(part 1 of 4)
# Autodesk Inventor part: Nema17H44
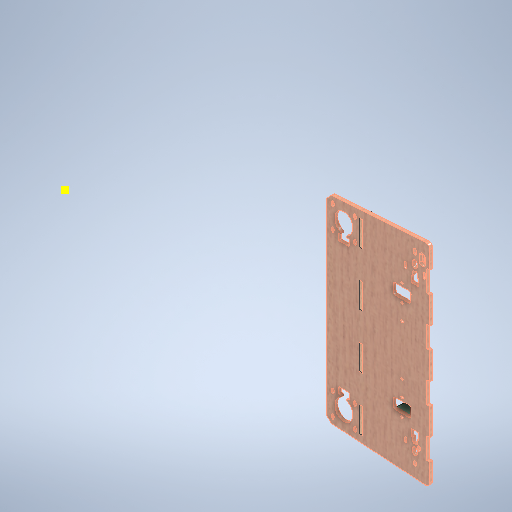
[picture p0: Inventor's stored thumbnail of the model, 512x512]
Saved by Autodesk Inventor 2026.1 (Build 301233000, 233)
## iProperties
Created: 2025-11
Part Number: Nema17H44
Material: Steel
Document SubType Name: Modeling
Designer: Yury Melnikov
Density: 7.85 g/cm^3
Appearance: Резина — зеленая
Mass: 34859.8 g
Surface Area: 7325.72 cm^2
Volume: 4440.74 cm^3
Sending System: Autodesk Translation Framework v14.17.0.0
Preprocessor: ST-DEVELOPER v20.1
Title: m2_20.step
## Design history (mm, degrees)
feature "Body3"
sketch "Эскиз1"
  geometry: L1 (0, 0)-(201.062, 0) reference; L2 (201.062, 0)-(201.062, 16) reference; L3 (0, 16)-(201.062, 16) reference; L4 (0, 0)-(0, 16) reference; C1 r 1.35 at (12.566, 8) reference; C2 r 1.35 at (100.531, 8) reference; C3 r 1.35 at (188.496, 8) reference; 1 further point
  dimensions: "d0" = 87.96459 distance of C2.centre C1.centre (derived); "d1" = 12.56644 distance from line of L4 C1.centre (derived); "d2" = 201.062 distance of L3.start L2.end (derived); "d3" = 16 distance of L1.start L3.start (derived); "d4" = 12.56637 distance from line of L2 C3.centre (derived)
  node "Спроецированная петля1"
pattern_linear "Прямоуг.массив1" dims "d11" = 201
sketch "Эскиз2"
  geometry: L1 (0, 3.5)-(0, 0) reference; L2 (0, 0)-(16, 0) reference; L3 (16, 3.5)-(16, 0) reference; L4 (0, 3.5)-(16, 3.5) reference; L5 (0, 0)-(16, 0); L6 (16, 0)-(16, -200); L7 (16, -200)-(0, -200); L8 (0, -200)-(0, 0); 2 further points
  constraints: 8 end point, 2 parallel, 1 horizontal, 1 perpendicular
  dimensions: "d5" = 16 distance of L6.end L7.end; "d6" = 200 distance of L5.end L6.end
extrude "Выдавливание1" new body sketch "Эскиз2" stored distance "d7" = 1000; taper "d8" = 0 deg
node "РабПлоскость1"
mirror "Зеркальное отражение1"
sketch "Эскиз3"
  geometry: L1 (158, 0)-(-142, 0); L2 (-142, 0)-(-142, 200); L3 (-142, 200)-(158, 200); L4 (158, 200)-(158, 0); L5 (16, 0)-(0, 0) reference; 3 further points
  constraints: 8 end point, 2 midpoint, 2 parallel, 1 coincident, 1 collinear, 1 horizontal, 1 perpendicular
  dimensions: "d12" = 300 distance of L1.start L1.end; "d13" = 200 distance of L1.end L2.end
extrude "Выдавливание2" join sketch "Эскиз3" distance "d14" = 16; taper "d15" = 0 deg
sketch "Эскиз4"
  geometry: L1 (0, 0)-(0, 200) reference; L2 (0, 100)-(107.784, 100); L3 (223.834, 208)-(222.148, 208) reference; L4 (184.75, 229.098)-(215.25, 229.098); L5 (215.25, 229.098)-(215.25, 198.598); L6 (215.25, 198.598)-(184.75, 198.598); L7 (184.75, 198.598)-(184.75, 229.098); L8 (183.233, 235.415)-(216.767, 235.415); L9 (221.567, 230.615)-(221.567, 192.281); L10 (221.567, 192.281)-(178.433, 192.281); L11 (178.433, 192.281)-(178.433, 230.615); L12 (178.433, 230.615)-(183.233, 235.415); L13 (216.767, 235.415)-(221.567, 230.615); L14 (216.767, -35.415)-(221.567, -30.615); L15 (215.25, -29.098)-(215.25, 1.402); L16 (184.75, -29.098)-(215.25, -29.098); L17 (183.233, -35.415)-(216.767, -35.415); L18 (221.567, -30.615)-(221.567, 7.719); L19 (178.433, -30.615)-(183.233, -35.415); L20 (215.25, 1.402)-(184.75, 1.402); L21 (221.567, 7.719)-(178.433, 7.719); L22 (184.75, 1.402)-(184.75, -29.098); L23 (178.433, 7.719)-(178.433, -30.615); L24 (223.834, -8)-(222.148, -8); L25 (343.215, 208)-(341.529, 208) reference; L26 (343.215, -8)-(341.529, -8); L27 (324.365, 208)-(322.679, 208) reference; L28 (321.041, 203.5)-(319.72, 203.5) reference; L29 (226.794, 203.5)-(225.472, 203.5) reference; C1 r 8 at (200, 213.848); C2 r 1.65 at (184.75, 229.098); C3 r 1.65 at (215.25, 229.098); C4 r 1.65 at (184.75, 198.598); C5 r 1.65 at (215.25, 198.598); C6 r 1.65 at (215.25, -29.098); C7 r 1.65 at (184.75, -29.098); C8 r 8 at (200, -13.848); C9 r 1.65 at (184.75, 1.402); C10 r 1.65 at (215.25, 1.402); C11 r 8 at (300, 213.848); C12 r 8 at (300, -13.848); A1 r 21.567 centre (200, 213.848) between (184.75, 229.098) and (215.25, 229.098); A2 r 21.567 centre (200, -13.848) between (184.75, -29.098) and (215.25, -29.098); 5 further points
  constraints: 46 end point, 23 symmetric about line, 14 centre point, 8 point on line, 6 point on circle, 4 coincident, 4 horizontal, 4 parallel, 4 tangent, 2 perpendicular, 1 midpoint, 1 vertical, 13 other
  dimensions: "d16" = 16 diameter of C1; "d18" = 30.5 distance of L5.end L6.end; "d19" = 30.5 distance of L4.end L5.end (= d18); "d22" = 30.5 distance of C2.centre C3.centre (= d18); "d25" = 30.5 distance of C2.centre C4.centre (= d19); "d28" = 3.3 diameter of C3; "d29" = 4.8 distance of L11.end point (178.433, 235.415); "d30" = 4.8 distance of L8.start point (178.433, 235.415) (= d29); "d31" = 4.8 distance of L8.end point (221.567, 235.415) (= d29); "d32" = 4.8 distance of L9.start point (221.567, 235.415) (= d31); "d33" = 16 diameter of C11; "d35" = 100 distance of C11.centre C1.centre (= h1); "d37" = 2.348 distance edge to line of C11 L28; "d38" = 2.348 distance edge to line of C1 L29 (= d37); "d41" = 200 distance from line of C1.centre L1 (= dist1)
extrude "Выдавливание3" new body sketch "Эскиз4" stored distance "d39" = 10; taper "d40" = 0 deg
node "РабПлоскость2"
sketch "Эскиз6"
  geometry: C1 r 8 at (0, 0) reference; C2 r 8 at (0, 227.696) reference; C3 r 8 at (100, 227.696) reference; C4 r 8 at (100, 0) reference; C5 r 4.05 at (0, 0); C6 r 4.05 at (0, 227.696); C7 r 2.95 at (100, 227.696); C8 r 2.95 at (100, 0); 1 further point
  constraints: 4 centre point, 4 coincident
  dimensions: "d42" = 8.1 diameter of C5; "d43" = 8.1 diameter of C6 (= d42); "d44" = 5.9 diameter of C7; "d45" = 5.9 diameter of C8 (= d44)
extrude "Выдавливание4" join sketch "Эскиз6" stored distance "d46" = 20; taper "d47" = 0 deg
sketch "Эскиз8"
  geometry: L1 (4, -18.424)-(-4, -18.424); L2 (-4, -18.424)-(-4, -22.424); L3 (-4, -22.424)-(4, -22.424); L4 (4, -22.424)-(4, -18.424); L5 (-200, -13.848)-(805.062, -13.848) reference; L6 (18, 0)-(-18, 0); L7 (-18, 0)-(-18, -22); L8 (-13, -27)-(13, -27); L9 (18, -22)-(18, 0); L10 (5.5, -17.924)-(-5.5, -17.924); L11 (-5.5, -17.924)-(-5.5, -22.924); L12 (-5.5, -22.924)-(5.5, -22.924); L13 (5.5, -22.924)-(5.5, -17.924); L14 (18, -13.848)-(18, -27); L15 (50, 0)-(50, -51.494); L16 (105.5, -17.924)-(105.5, -22.924); L17 (104, -18.424)-(104, -22.424); L18 (118, 0)-(118, -22); L19 (96, -18.424)-(104, -18.424); L20 (96, -22.424)-(96, -18.424); L21 (104, -22.424)-(96, -22.424); L22 (94.5, -22.924)-(94.5, -17.924); L23 (105.5, -22.924)-(94.5, -22.924); L24 (94.5, -17.924)-(105.5, -17.924); L25 (113, -27)-(87, -27); L26 (82, -13.848)-(82, -22); L27 (82, 0)-(118, 0); L28 (82, -27)-(82, 0); L29 (2.85, -10.848)-(-2.85, -10.848); L30 (-2.85, -10.848)-(-2.85, -13.848); L31 (-2.85, -13.848)-(2.85, -13.848); L32 (2.85, -13.848)-(2.85, -10.848); L33 (300, -13.848)-(-705.062, -13.848); L34 (97.15, -10.848)-(102.85, -10.848); L35 (102.85, -13.848)-(97.15, -13.848); L36 (97.15, -13.848)-(97.15, -10.848); L37 (102.85, -10.848)-(102.85, -13.848); L38 (-200, -213.848)-(-200, -13.848) reference; L39 (-200, -113.848)-(-37.521, -113.848); L40 (4, -209.272)-(-4, -209.272); L41 (-4, -209.272)-(-4, -205.272); L42 (18, -205.696)-(18, -227.696); L43 (18, -213.848)-(18, -200.696); L44 (4, -205.272)-(4, -209.272); L45 (-4, -205.272)-(4, -205.272); L46 (102.85, -216.848)-(102.85, -213.848); L47 (102.85, -213.848)-(97.15, -213.848); L48 (104, -209.272)-(104, -205.272); L49 (113, -200.696)-(87, -200.696); L50 (105.5, -209.772)-(105.5, -204.772); L51 (-13, -200.696)-(13, -200.696); L52 (5.5, -209.772)-(-5.5, -209.772); L53 (-5.5, -209.772)-(-5.5, -204.772); L54 (-5.5, -204.772)-(5.5, -204.772); L55 (5.5, -204.772)-(5.5, -209.772); L56 (2.85, -213.848)-(2.85, -216.848); L57 (2.85, -216.848)-(-2.85, -216.848); L58 (-2.85, -213.848)-(2.85, -213.848); L59 (96, -205.272)-(96, -209.272); L60 (94.5, -204.772)-(94.5, -209.772); L61 (104, -205.272)-(96, -205.272); L62 (96, -209.272)-(104, -209.272); L63 (105.5, -204.772)-(94.5, -204.772); L64 (94.5, -209.772)-(105.5, -209.772)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; C1 r 4.05 at (0, 0) reference; C2 r 3.05 at (0, 0); C3 r 6.1 at (0, 0); C4 r 2.95 at (100, 0) reference; C5 r 2.95 at (100, -227.696) reference; C6 r 4.05 at (100, 0); C7 r 3.05 at (100, 0); C8 r 4.05 at (100, 0); C9 r 4.05 at (0, -227.696); C10 r 3.05 at (0, -227.696); C11 r 6.1 at (0, -227.696); C12 r 2.95 at (100, -227.696); C13 r 4.05 at (100, -227.696); C14 r 3.05 at (100, -227.696); C15 r 4.05 at (100, -227.696); A1 r 18 centre (0, 0) between (18, 0) and (-18, 0); A2 r 4.472 centre (0, -20.424) between (4, -18.424) and (-4, -22.424); A3 r 6.042 centre (0, -20.424) between (5.5, -17.924) and (5.5, -22.924); A4 r 4.472 centre (100, -20.424) between (96, -18.424) and (104, -22.424); A5 r 6.042 centre (100, -20.424) between (94.5, -17.924) and (94.5, -22.924); A6 r 18 centre (100, 0) between (118, 0) and (82, 0); A7 r 5 centre (113, -22) between (113, -27) and (118, -22); A8 r 5 centre (87, -22) between (82, -22) and (87, -27); A9 r 5 centre (13, -22) between (13, -27) and (18, -22); A10 r 5 centre (-13, -22) between (-18, -22) and (-13, -27); A11 r 5 centre (113, -205.696) between (118, -205.696) and (113, -200.696); A12 r 4.472 centre (0, -207.272) between (4, -209.272) and (-4, -205.272); A13 r 6.042 centre (0, -207.272) between (5.5, -209.772) and (5.5, -204.772); A14 r 5 centre (13, -205.696) between (18, -205.696) and (13, -200.696); A15 r 4.472 centre (100, -207.272) between (96, -209.272) and (104, -205.272); A16 r 6.042 centre (100, -207.272) between (94.5, -209.772) and (94.5, -204.772); A17 r 5 centre (-13, -205.696) between (-13, -200.696) and (-18, -205.696); A18 r 18 centre (0, -227.696) between (-18, -227.696) and (18, -227.696); A19 r 18 centre (100, -227.696) between (82, -227.696) and (118, -227.696); A20 r 5 centre (87, -205.696) between (87, -200.696) and (82, -205.696); 29 further points
  constraints: 144 end point, 102 symmetric about line, 49 point on circle, 32 centre point, 21 point on line, 18 coincident, 10 tangent, 8 parallel, 5 horizontal, 5 midpoint, 5 perpendicular, 3 equal radius, 2 horizontal alignment, 2 vertical alignment, 1 vertical, 22 other
  dimensions: "d52" = 8 distance of L3.end L2.end; "d53" = 4 distance of L2.end L1.end; "d55" = 5 distance of L12.end L10.start; "d56" = 11 distance of L11.end L12.end; "d57" = 12.2 diameter of C3; "d58" = 6.1 diameter of C2; "d60" = 36 distance of point (-18, -27) L14.end; "d61" = 45 distance from line of point (0, 18) L8; "d62" = 50 distance of point (0, 0) L15.start (= 0.5 x h1); "d63" = 8.1 diameter of C8; "d64" = 5 radius of A7; "d65" = 3 distance of L31.end L29.start; "d66" = 5.7 distance of L30.end L31.end
extrude "Выдавливание5" new body sketch "Эскиз8" distance "d67" = 4; taper "d68" = 0 deg
sketch "Эскиз10"
  geometry: L1 (182, -18)-(218, -18) reference; L2 (218, -18)-(218, -22) reference; L3 (250, -75.177)-(250, -31.883); C1 r 1.5 at (200, -20); C2 r 1.5 at (300, -20); 3 further points
  constraints: 2 centre point, 2 end point, 2 midpoint, 1 horizontal alignment, 1 symmetric about line, 1 vertical, 1 vertical alignment, 1 other
  dimensions: "d70" = 3 diameter of C1; "d71" = 50 distance from line of C1.centre L3 (= 0.5 x h1)
extrude "Выдавливание6" cut sketch "Эскиз10" stored distance "d72" = 213.75; taper "d73" = 0 deg
chamfer "Фаска1" distance "d74" = 1; stored, may be unused: second distance "d75" = 2, angle "d76" = 45 deg
mirror "Зеркальное отражение2"
sketch "Эскиз11"
  geometry: L1 (-118, 227.696)-(-118, 205.696) reference; L2 (-82, 205.696)-(-82, 227.696) reference; L3 (-113, 200.696)-(-87, 200.696) reference; L4 (-96.15, 213.848)-(-103.85, 213.848) reference; L5 (-96.15, 216.848)-(-96.15, 213.848) reference; L6 (-103.85, 216.848)-(-96.15, 216.848) reference; L7 (-103.85, 213.848)-(-103.85, 216.848) reference; L8 (-94.5, 209.772)-(-94.5, 204.772) reference; L9 (-105.5, 209.772)-(-94.5, 209.772) reference; L10 (-105.5, 204.772)-(-105.5, 209.772) reference; L11 (-94.5, 204.772)-(-105.5, 204.772) reference; L12 (-82, 205.696)-(-82, 227.696) reference; L13 (-82, 223.696)-(-88.686, 223.696); L14 (-111.314, 223.696)-(-118, 223.696); L15 (-50, 113.848)-(-50, 178.448); L16 (-50, 113.848)-(-5.069, 113.848); L17 (-100, 0)-(-100, 227.696); L18 (-18, 223.696)-(-11.314, 223.696); L19 (-18, 205.696)-(-18, 227.696); L20 (11.314, 223.696)-(18, 223.696); L21 (-18, 4)-(-11.314, 4); L22 (11.314, 4)-(18, 4); L23 (-18, 22)-(-18, 0); L24 (-111.314, 4)-(-118, 4); L25 (-103.85, 10.848)-(-96.15, 10.848); L26 (-96.15, 10.848)-(-96.15, 13.848); L27 (-103.85, 13.848)-(-103.85, 10.848); L28 (-118, 0)-(-118, 22); L29 (-105.5, 17.924)-(-94.5, 17.924); L30 (-113, 27)-(-87, 27); L31 (-94.5, 22.924)-(-105.5, 22.924); L32 (-94.5, 17.924)-(-94.5, 22.924); L33 (-96.15, 13.848)-(-103.85, 13.848); L34 (-82, 22)-(-82, 0); L35 (-82, 4)-(-88.686, 4); L36 (-82, 22)-(-82, 0); L37 (-105.5, 22.924)-(-105.5, 17.924); L38 (18, 227.696)-(18, 223.696); L39 (-18, 227.696)-(-18, 223.696); L40 (18, 4)-(18, 0); L41 (-18, 4)-(-18, 0); C1 r 6.1 at (-100, 227.696) reference; C2 r 11 at (-100, 227.696); C3 r 6.1 at (-100, 227.696) reference; C4 r 8 at (-100, 227.696); C5 r 4 at (-100, 227.696); C6 r 6.1 at (-100, 0) reference; C7 r 6.1 at (0, 227.696); C8 r 11 at (0, 227.696); C9 r 4 at (0, 227.696); C10 r 6.1 at (0, 227.696); C11 r 8 at (0, 227.696); C12 r 4 at (0, 0); C13 r 6.1 at (0, 0); C14 r 6.1 at (0, 0); C15 r 8 at (0, 0); C16 r 11 at (0, 0); C17 r 6.1 at (-100, 0); C18 r 11 at (-100, 0); C19 r 4 at (-100, 0); C20 r 6.1 at (-100, 0); C21 r 8 at (-100, 0); A1 r 18 centre (-100, 227.696) between (-82, 227.696) and (-118, 227.696) reference; A2 r 5 centre (-87, 205.696) between (-87, 200.696) and (-82, 205.696) reference; A3 r 5 centre (-113, 205.696) between (-118, 205.696) and (-113, 200.696) reference; A4 r 12 centre (-100, 227.696) between (-88.686, 223.696) and (-111.314, 223.696); A5 r 18 centre (0, 227.696) between (18, 227.696) and (-18, 227.696); A6 r 12 centre (0, 227.696) between (11.314, 223.696) and (-11.314, 223.696); A7 r 12 centre (0, 0) between (-11.314, 4) and (11.314, 4); A8 r 18 centre (0, 0) between (-18, 0) and (18, 0); A9 r 18 centre (-100, 0) between (-118, 0) and (-82, 0); A10 r 12 centre (-100, 0) between (-111.314, 4) and (-88.686, 4); A11 r 5 centre (-113, 22) between (-113, 27) and (-118, 22); A12 r 5 centre (-87, 22) between (-82, 22) and (-87, 27); 6 further points
  constraints: 58 end point, 51 symmetric about line, 27 centre point, 18 point on circle, 13 point on line, 12 coincident, 3 parallel, 3 tangent, 3 vertical, 1 horizontal, 1 midpoint, 1 perpendicular, 23 other
  dimensions: "d77" = 22 diameter of C2; "d80" = 16 diameter of C4; "d81" = 8 diameter of C5; "d82" = 12 radius of A4; "d83" = 50 distance from line of C1.centre L15 (= 0.5 x h1)
extrude "Выдавливание7" join sketch "Эскиз11" stored distance "d84" = 213.75; taper "d85" = 0 deg
fillet "Сопряжение1" dims "d86" = 2
sketch "Эскиз12"
  geometry: L1 (0, -18)-(0, -12); L2 (300, 13.848)-(300, 213.848) reference; L3 (300, 113.848)-(202.743, 113.848); L4 (0, 245.696)-(0, 239.696); C1 r 4.05 at (0, 0) reference; C2 r 2 at (0, -15); C3 r 2 at (12.99, 7.5); C4 r 2 at (-12.99, 7.5); C5 r 2 at (12.99, 220.196); C6 r 4.05 at (0, 227.696); C7 r 2 at (0, 242.696); C8 r 2 at (-12.99, 220.196); A1 r 12 centre (0, 0) between (-11.314, 4) and (11.314, 4) reference; A2 r 18 centre (0, 0) between (-18, 0) and (18, 0) reference; A3 r 12 centre (0, 227.696) between (11.314, 223.696) and (-11.314, 223.696); A4 r 18 centre (0, 227.696) between (18, 227.696) and (-18, 227.696); 9 further points
  constraints: 16 symmetric about line, 9 centre point, 6 end point, 6 point on circle, 4 coincident, 2 horizontal, 2 midpoint, 2 vertical alignment, 20 other
  dimensions: "d92" = 360 deg dimension on C1.centre C2.centre (derived); "d94" = 4 diameter of C2
extrude "Выдавливание8" cut sketch "Эскиз12" distance "d95" = 5; taper "d96" = 0 deg
chamfer "Фаска2" distance "d97" = 0.7; stored, may be unused: second distance "d98" = 2, angle "d99" = 45 deg
sketch "Эскиз13"
  geometry: L1 (-15.55, -15.55)-(15.55, -15.55); L2 (15.55, -15.55)-(15.55, 15.55); L3 (15.55, 15.55)-(-15.55, 15.55); L4 (-15.55, 15.55)-(-15.55, -15.55); L5 (-16.2, -22)-(16.2, -22); L6 (21, -17.2)-(21, 17.2); L7 (16.2, 22)-(-16.2, 22); L8 (-21, 17.2)-(-21, -17.2); L9 (21, -17.2)-(16.2, -22); L10 (-21, -17.2)-(-16.2, -22); L11 (-21, 17.2)-(-16.2, 22); L12 (16.2, 22)-(21, 17.2); L13 (18, 22)-(18, 0) reference; L14 (-13, 27)-(13, 27) reference; L15 (-18, 0)-(-18, 22) reference; L16 (-3.85, 10.848)-(3.85, 10.848) reference; L17 (-3.85, 13.848)-(-3.85, 10.848) reference; L18 (3.85, 13.848)-(-3.85, 13.848) reference; L19 (3.85, 10.848)-(3.85, 13.848) reference; L20 (-5.5, 17.924)-(5.5, 17.924) reference; L21 (-5.5, 22.924)-(-5.5, 17.924) reference; L22 (5.5, 22.924)-(-5.5, 22.924) reference; L23 (5.5, 17.924)-(5.5, 22.924) reference; C1 r 1.65 at (-15.55, -15.55); C2 r 1.65 at (15.55, -15.55); C3 r 1.65 at (-15.55, 15.55); C4 r 1.65 at (15.55, 15.55); C5 r 4.05 at (0, 0) reference; C6 r 6.1 at (0, 0) reference; A1 r 21.991 centre (0, 0) between (-15.55, -15.55) and (-15.55, 15.55); A2 r 5 centre (13, 22) between (18, 22) and (13, 27) reference; A3 r 5 centre (-13, 22) between (-13, 27) and (-18, 22) reference; A4 r 18 centre (0, 0) between (-18, 0) and (18, 0) reference; 11 further points
  constraints: 24 end point, 8 point on line, 5 centre point, 4 midpoint, 4 parallel, 3 horizontal, 3 point on circle, 2 perpendicular, 1 coincident, 1 concentric, 1 horizontal alignment, 1 vertical, 1 vertical alignment, 6 other
  dimensions: "d100" = 31.1 distance of L3.end L2.end (derived); "d101" = 31.1 distance of L2.end L1.end; "d102" = 42 distance of point (-21, 22) point (21, 22); "d103" = 44 distance of point (21, 22) point (21, -22); "d106" = 31.1 distance of C1.centre C2.centre (derived); "d109" = 31.1 distance of C1.centre C3.centre (derived); "d112" = 3.3 diameter of C1; "d113" = 4.8 distance of L6.start point (21, -22); "d114" = 4.8 distance of L5.end point (21, -22) (derived); "d115" = 4.8 distance of L8.end point (-21, -22) (derived); "d116" = 4.8 distance of L5.start point (-21, -22) (derived); "d117" = 4.8 distance of L8.start point (-21, 22) (derived); "d118" = 4.8 distance of L7.end point (-21, 22) (derived); "d119" = 4.8 distance of L7.start point (21, 22) (derived); "d120" = 4.8 distance of L6.end point (21, 22) (derived)
extrude "Выдавливание9" join sketch "Эскиз13" distance "d121" = 4; taper "d122" = 0 deg
fillet "Сопряжение2" dims "d123" = 5
sketch "Эскиз14"
  geometry: L1 (-2.55, -42.55)-(28.55, -42.55); L2 (28.55, -42.55)-(28.55, -11.45); L3 (28.55, -11.45)-(-2.55, -11.45); L4 (-2.55, -11.45)-(-2.55, -42.55); C1 r 1.65 at (-2.55, -42.55) reference; C2 r 1.65 at (28.55, -42.55) reference; C3 r 1.65 at (-2.55, -11.45); C4 r 1.65 at (28.55, -11.45); 1 further point
  constraints: 8 end point, 3 coincident, 2 centre point, 2 equal radius, 2 parallel, 2 perpendicular, 1 horizontal
extrude "Выдавливание10" cut sketch "Эскиз14" distance "d124" = 4; taper "d125" = 0 deg
chamfer "Фаска3" distance "d126" = 2; stored, may be unused: second distance "d127" = 2, angle "d128" = 45 deg
mirror "Зеркальное отражение3"
fillet "Сопряжение3" dims "d129" = 3
fillet "Сопряжение4" dims "d130" = 3
fillet "Сопряжение5" dims "d131" = 2
sketch "Эскиз16"
  geometry: 1 further point
fillet "Сопряжение6" dims "d132" = 2
sketch "Эскиз17"
  geometry: L1 (87, 27)-(113, 27) reference; L2 (80.539, 18.739)-(79, 17.2) reference; L3 (79, 17.2)-(79, -17.2) reference; L4 (79, -17.2)-(83.8, -22) reference; L5 (83.8, -22)-(116.2, -22) reference; L6 (116.2, -22)-(121, -17.2) reference; L7 (121, -17.2)-(121, 17.2) reference; L8 (121, 17.2)-(119.461, 18.739) reference; L9 (96.15, 10.848)-(103.85, 10.848) reference; L10 (96.15, 13.848)-(96.15, 10.848) reference; L11 (103.85, 13.848)-(96.15, 13.848) reference; L12 (103.85, 10.848)-(103.85, 13.848) reference; L13 (92.5, 17.924)-(107.5, 17.924) reference; L14 (92.5, 22.924)-(92.5, 17.924) reference; L15 (107.5, 22.924)-(92.5, 22.924) reference; L16 (107.5, 17.924)-(107.5, 22.924) reference; L17 (-3.85, 10.848)-(3.85, 10.848); L18 (-3.85, 13.848)-(-3.85, 10.848); L19 (3.85, 13.848)-(-3.85, 13.848); L20 (3.85, 10.848)-(3.85, 13.848); L21 (-7.5, 17.924)-(7.5, 17.924); L22 (-7.5, 22.924)-(-7.5, 17.924); L23 (7.5, 22.924)-(-7.5, 22.924); L24 (7.5, 17.924)-(7.5, 22.924); L25 (-13, 27)-(13, 27); L26 (-18, 0)-(-18, 22); L27 (18, 22)-(18, 0); L28 (113, 200.696)-(87, 200.696) reference; L29 (121, 210.496)-(119.461, 208.957) reference; L30 (121, 244.896)-(121, 210.496) reference; L31 (116.2, 249.696)-(121, 244.896) reference; L32 (83.8, 249.696)-(116.2, 249.696) reference; L33 (79, 244.896)-(83.8, 249.696) reference; L34 (79, 210.496)-(79, 244.896) reference; L35 (80.539, 208.957)-(79, 210.496) reference; L36 (96.15, 213.848)-(103.85, 213.848) reference; L37 (96.15, 216.848)-(96.15, 213.848) reference; L38 (103.85, 216.848)-(96.15, 216.848) reference; L39 (103.85, 213.848)-(103.85, 216.848) reference; L40 (92.5, 204.772)-(107.5, 204.772) reference; L41 (92.5, 209.772)-(92.5, 204.772) reference; L42 (107.5, 209.772)-(92.5, 209.772) reference; L43 (107.5, 204.772)-(107.5, 209.772) reference; L44 (121, 210.496)-(121, 17.2); L45 (-7.5, 209.772)-(-7.5, 204.772) reference; L46 (7.5, 209.772)-(-7.5, 209.772) reference; L47 (-7.5, 204.772)-(7.5, 204.772) reference; L48 (7.5, 204.772)-(7.5, 209.772) reference; L49 (3.85, 213.848)-(3.85, 216.848) reference; L50 (-3.85, 213.848)-(3.85, 213.848) reference; L51 (-3.85, 216.848)-(-3.85, 213.848) reference; L52 (3.85, 216.848)-(-3.85, 216.848) reference; L53 (116.2, -22)-(-18, -31.152); L54 (-18, -31.152)-(-18, 258.848); L55 (-18, 258.848)-(116.2, 249.696); C1 r 1.65 at (115.55, 15.55) reference; C2 r 1.65 at (84.45, 15.55) reference; C3 r 1.65 at (115.55, -15.55) reference; C4 r 1.65 at (84.45, -15.55) reference; C5 r 6.1 at (100, 0) reference; C6 r 2.7 at (-12.99, 7.5); C7 r 4.05 at (0, 0); C8 r 2.7 at (0, -15); C9 r 2.7 at (12.99, 7.5); C10 r 1.65 at (115.55, 212.146) reference; C11 r 1.65 at (84.45, 212.146) reference; C12 r 1.65 at (115.55, 243.246) reference; C13 r 1.65 at (84.45, 243.246) reference; C14 r 6.1 at (100, 227.696) reference; C15 r 2 at (0, -15) reference; C16 r 2 at (12.99, 7.5) reference; C17 r 2 at (12.99, 220.196) reference; C18 r 2 at (0, 242.696) reference; C19 r 1.65 at (84.45, 212.146) reference; C20 r 1.65 at (84.45, 243.246) reference; C21 r 1.65 at (115.55, 243.246) reference; C22 r 1.65 at (115.55, 212.146) reference; C23 r 1.65 at (115.55, 15.55) reference; C24 r 1.65 at (115.55, -15.55) reference; C25 r 1.65 at (84.45, -15.55) reference; C26 r 1.65 at (84.45, 15.55) reference; C27 r 4.05 at (100, 0) reference; C28 r 12 at (100, 0); C29 r 12 at (100, 227.696); C30 r 1.4 at (84.45, -15.55); C31 r 1.4 at (84.45, 15.55); C32 r 1.4 at (115.55, 15.55); C33 r 1.4 at (115.55, -15.55); C34 r 1.4 at (84.45, 212.146); C35 r 1.4 at (84.45, 243.246); C36 r 1.4 at (115.55, 243.246); C37 r 1.4 at (115.55, 212.146); C38 r 1.4 at (0, 242.696); C39 r 1.4 at (12.99, 220.196); C40 r 1.4 at (0, -15); C41 r 1.4 at (12.99, 7.5); C42 r 3 at (0, 0); C43 r 3 at (0, 227.696); A1 r 5 centre (113, 22) between (117.998, 22.137) and (113, 27) reference; A2 r 5 centre (87, 22) between (87, 27) and (82.002, 22.137) reference; A3 r 5 centre (77.004, 22.275) between (80.539, 18.739) and (82.002, 22.137) reference; A4 r 5 centre (122.996, 22.275) between (117.998, 22.137) and (119.461, 18.739) reference; A5 r 5 centre (13, 22) between (18, 22) and (13, 27); A6 r 5 centre (-13, 22) between (-13, 27) and (-18, 22); A7 r 5 centre (87, 205.696) between (82.002, 205.559) and (87, 200.696) reference; A8 r 5 centre (113, 205.696) between (113, 200.696) and (117.998, 205.559) reference; A9 r 5 centre (122.996, 205.421) between (119.461, 208.957) and (117.998, 205.559) reference; A10 r 5 centre (77.004, 205.421) between (82.002, 205.559) and (80.539, 208.957) reference; 12 further points
  constraints: 22 centre point, 15 coincident, 8 end point, 8 equal radius, 2 vertical, 1 collinear, 1 equal length
  dimensions: "d133" = 24 diameter of C28; "d134" = 2.8 diameter of C30; "d135" = 2.8 diameter of C34 (derived); "d138" = 6 diameter of C42; "d139" = 6 diameter of C43; "d189" = 290 distance of L53.end L54.end
extrude "Выдавливание11" new body sketch "Эскиз17" distance "d140" = 4; taper "d141" = 0 deg
chamfer "Фаска5" distance "d145" = 1; stored, may be unused: second distance "d146" = 2, angle "d147" = 45 deg
sketch "Эскиз18"
  geometry: L1 (96.15, 12.417)-(96.15, 13.848) reference; L2 (96.15, 13.848)-(103.85, 13.848) reference; L3 (103.85, 13.848)-(103.85, 12.417) reference; L4 (103.85, 215.279)-(103.85, 213.848) reference; L5 (103.85, 213.848)-(96.15, 213.848) reference; L6 (96.15, 213.848)-(96.15, 215.279) reference; L7 (3.85, 213.848)-(-3.85, 213.848) reference; L8 (-3.85, 213.848)-(-3.85, 216.848) reference; L9 (-3.85, 216.848)-(3.85, 216.848) reference; L10 (3.85, 216.848)-(3.85, 213.848) reference; L11 (-7.5, 209.772)-(7.5, 209.772) reference; L12 (7.5, 209.772)-(7.5, 204.772) reference; L13 (7.5, 204.772)-(-7.5, 204.772) reference; L14 (-7.5, 204.772)-(-7.5, 209.772) reference; L15 (92.5, 204.772)-(92.5, 209.772) reference; L16 (92.5, 209.772)-(107.5, 209.772) reference; L17 (107.5, 209.772)-(107.5, 204.772) reference; L18 (107.5, 204.772)-(92.5, 204.772) reference; L19 (-7.5, 17.924)-(-7.5, 22.924) reference; L20 (-7.5, 22.924)-(7.5, 22.924) reference; L21 (7.5, 22.924)-(7.5, 17.924) reference; L22 (7.5, 17.924)-(-7.5, 17.924) reference; L23 (-3.85, 10.848)-(-3.85, 13.848) reference; L24 (-3.85, 13.848)-(3.85, 13.848) reference; L25 (3.85, 13.848)-(3.85, 10.848) reference; L26 (3.85, 10.848)-(-3.85, 10.848) reference; L27 (92.5, 17.924)-(92.5, 22.924) reference; L28 (92.5, 22.924)-(107.5, 22.924) reference; L29 (107.5, 22.924)-(107.5, 17.924) reference; L30 (107.5, 17.924)-(92.5, 17.924) reference; L31 (-18, 258.848)-(-18, -31.152) reference; L32 (116.2, -22)-(121, -17.2) reference; L33 (121, -17.2)-(121, 244.896) reference; L34 (121, 244.896)-(116.2, 249.696) reference; L35 (116.2, 249.696)-(-18, 258.848) reference; L36 (-18, -31.152)-(116.2, -22) reference; L37 (124, 246.139)-(124, -18.443); L38 (124, -18.443)-(117.526, -24.917); L39 (117.526, -24.917)-(-21, -34.364); L40 (-21, -34.364)-(-21, 262.06); L41 (-21, 262.06)-(117.526, 252.613); L42 (117.526, 252.613)-(124, 246.139); C1 r 1.4 at (115.55, 212.146) reference; C2 r 1.4 at (84.45, 243.246) reference; C3 r 1.4 at (115.55, -15.55) reference; C4 r 1.4 at (115.55, 15.55) reference; C5 r 1.4 at (84.45, 15.55) reference; C6 r 1.4 at (84.45, -15.55) reference; C7 r 1.4 at (84.45, 212.146) reference; C8 r 1.4 at (115.55, 243.246) reference; C9 r 3 at (0, 227.696) reference; C10 r 3 at (0, 0) reference; A1 r 13 centre (100, 0) between (96.15, 12.417) and (103.85, 12.417) reference; A2 r 13 centre (100, 227.696) between (103.85, 215.279) and (96.15, 215.279) reference; 1 further point
  constraints: 12 end point, 5 other
  dimensions: "d190" = 3 distance between parallel lines of L35 L41
extrude "Выдавливание12" join sketch "Эскиз18" distance "d149" = 4; taper "d150" = 0 deg
chamfer "Фаска7" distance "d154" = 1; stored, may be unused: second distance "d155" = 2, angle "d156" = 45 deg
sketch "Эскиз19"
  geometry: L1 (-16.8, 61.348)-(53.2, 61.348); L2 (53.2, 61.348)-(53.2, 166.348); L3 (53.2, 166.348)-(-16.8, 166.348); L4 (-16.8, 166.348)-(-16.8, 61.348); L5 (124, -18.443)-(124, 246.139) reference; L6 (-21, 262.06)-(-21, -34.364) reference; L7 (18.2, 78.848)-(18.2, 148.848); C1 r 1.6 at (18.2, 78.848); C2 r 1.6 at (18.2, 148.848); 6 further points
  constraints: 10 end point, 5 midpoint, 2 centre point, 2 horizontal alignment, 2 parallel, 2 vertical alignment, 1 coincident, 1 equal radius, 1 horizontal, 1 perpendicular, 1 vertical
  dimensions: "d157" = 105 distance of L3.end L1.start; "d158" = 70 distance of L2.end L3.end; "d1054" = 4.2 distance between parallel lines of L4 L6; "d1055" = 70 distance of L7.start L7.end; "d1056" = 3.2 diameter of C2
extrude "Выдавливание13" new body sketch "Эскиз19" distance "d159" = 50; taper "d160" = 0 deg
chamfer "Фаска8" distance "d161" = 3; stored, may be unused: second distance "d162" = 2, angle "d163" = 45 deg
node "РабПлоскость3"
fillet "Сопряжение7" dims "d196" = 6
node "РабПлоскость4"
sketch "Эскиз20"
  geometry: L1 (-338, 5)-(-338, 195); L2 (-313.8, 50.5)-(-313.8, 149.5) reference; L3 (-329, -4)-(-321, -4); L4 (-321, -4)-(-321, 27); L5 (-321, 27)-(-329, 27); L6 (-329, 27)-(-329, -4); L7 (-309.6, -39)-(-269.6, -39); L8 (-269.6, -39)-(-269.6, 5); L9 (-269.6, 5)-(-309.6, 5); L10 (-309.6, 5)-(-309.6, -39); L11 (-309.6, -17)-(-354.4, -17); L12 (-342, -25)-(-326, -25); L13 (-326, -9)-(-342, -9); L14 (-321, -13.848)-(-321, 213.848) reference; L15 (-340, -25)-(-332, -25); L16 (-332, -9)-(-340, -9); L17 (-355.327, -52.761)-(-55.327, -52.761); L18 (-55.327, -52.761)-(-55.327, 247.239); L19 (-55.327, 247.239)-(-355.327, 247.239); L20 (-355.327, 247.239)-(-355.327, -52.761); L21 (-309.6, -17)-(-332, -17); L22 (-182.474, 238.765)-(-314.592, 247.775) reference; L23 (-321, 241.788)-(-321, -41.788) reference; L24 (-314.592, -47.775)-(-182.474, -38.765) reference; L25 (-182.474, -38.765)-(-176, -32.291) reference; L26 (-176, -32.291)-(-176, 232.291) reference; L27 (-176, 232.291)-(-182.474, 238.765) reference; L28 (-203.85, -1.431)-(-203.85, 0) reference; L29 (-203.85, 0)-(-196.15, 0) reference; L30 (-196.15, 0)-(-196.15, -1.431) reference; L31 (-207.5, 4.076)-(-207.5, 9.076) reference; L32 (-207.5, 9.076)-(-192.5, 9.076) reference; L33 (-192.5, 9.076)-(-192.5, 4.076) reference; L34 (-192.5, 4.076)-(-207.5, 4.076) reference; L35 (-303.85, -3)-(-303.85, 0) reference; L36 (-303.85, 0)-(-296.15, 0) reference; L37 (-296.15, 0)-(-296.15, -3) reference; L38 (-296.15, -3)-(-303.85, -3) reference; L39 (-307.5, 4.076)-(-307.5, 9.076) reference; L40 (-307.5, 9.076)-(-292.5, 9.076) reference; L41 (-292.5, 9.076)-(-292.5, 4.076) reference; L42 (-292.5, 4.076)-(-307.5, 4.076) reference; L43 (-207.5, 190.924)-(-207.5, 195.924) reference; L44 (-207.5, 195.924)-(-192.5, 195.924) reference; L45 (-192.5, 195.924)-(-192.5, 190.924) reference; L46 (-192.5, 190.924)-(-207.5, 190.924) reference; L47 (-307.5, 195.924)-(-292.5, 195.924) reference; L48 (-292.5, 195.924)-(-292.5, 190.924) reference; L49 (-292.5, 190.924)-(-307.5, 190.924) reference; L50 (-307.5, 190.924)-(-307.5, 195.924) reference; L51 (-296.15, 200)-(-303.85, 200) reference; L52 (-303.85, 200)-(-303.85, 203) reference; L53 (-303.85, 203)-(-296.15, 203) reference; L54 (-296.15, 203)-(-296.15, 200) reference; L55 (-196.15, 201.431)-(-196.15, 200) reference; L56 (-196.15, 200)-(-203.85, 200) reference; L57 (-203.85, 200)-(-203.85, 201.431) reference; L58 (-318, -45)-(-318, 245); L59 (-318, 245)-(-183.8, 235.848); L60 (-183.8, 235.848)-(-179, 231.048); L61 (-179, 231.048)-(-179, -31.048); L62 (-179, -31.048)-(-183.8, -35.848); L63 (-183.8, -35.848)-(-318, -45); L64 (-309.6, -39)-(-313.6, -39)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; C1 r 9 at (-338, 5); C2 r 3 at (-300, -13.848) reference; C3 r 1.4 at (-184.45, 229.398) reference; C4 r 1.4 at (-215.55, 198.298) reference; C5 r 1.4 at (-215.55, -29.398) reference; C6 r 1.4 at (-215.55, 1.702) reference; C7 r 1.4 at (-184.45, 1.702) reference; C8 r 1.4 at (-184.45, -29.398) reference; C9 r 1.4 at (-215.55, 229.398) reference; C10 r 1.4 at (-184.45, 198.298) reference; C11 r 3 at (-300, 213.848) reference; C12 r 9 at (-338, 195); A1 r 13 centre (-200, -13.848) between (-203.85, -1.431) and (-196.15, -1.431) reference; A2 r 13 centre (-200, 213.848) between (-196.15, 201.431) and (-203.85, 201.431) reference; A3 r 6 centre (-315, 241.788) between (-314.592, 247.775) and (-321, 241.788) reference; A4 r 6 centre (-315, -41.788) between (-321, -41.788) and (-314.592, -47.775) reference; A5 r 3 centre (-315, 241.788) between (-314.796, 244.781) and (-318, 241.788); A6 r 3 centre (-315, -41.788) between (-318, -41.788) and (-314.796, -44.781); 4 further points
  constraints: 110 end point, 22 parallel, 13 horizontal, 10 perpendicular, 5 collinear, 5 midpoint, 5 point on line, 4 centre point, 4 point on circle, 4 tangent, 2 equal length, 2 horizontal alignment, 1 coincident, 1 equal radius, 1 vertical, 12 other
  dimensions: "d166" = 18 diameter of C1; "d167" = 190 distance of L1.start L1.end; "d168" = 31 distance of L5.end L3.start; "d169" = 44 distance of L8.end L7.end; "d170" = 40 distance of L7.start L7.end; "d171" = 16 distance of L13.end L12.start; "d172" = 8 distance of L4.end L5.end; "d173" = 14 distance from line of L13 L1.start; "d184" = 300 distance of L19.end L18.end; "d185" = 300 distance of L18.end L17.end; "d188" = 22.4 distance of L21.start L21.end; "d191" = 3 distance between parallel lines of L58 L23; "d192" = 4 distance of L65.end L66.end; "d193" = 16 distance of L74.end L73.end; "d194" = 16 distance of L73.end L72.end; "d195" = 5 distance from line of L70.end L72; "d197" = 3 distance between parallel lines of L23 L76; "d198" = 2 distance between parallel lines of L12 L82; "d199" = 6 diameter of L89 L11
  node "Спроецированная петля16"
sketch "Эскиз22"
  geometry: L1 (0, 0)-(0, 200) reference; L2 (0, 200)-(-16, 200) reference; L3 (-16, 0)-(-16, 200) reference; L4 (0, 0)-(-16, 0) reference; 1 further point
extrude "Выдавливание14" cut sketch "Эскиз22" stored distance "d175" = 20; taper "d176" = 0 deg
sketch "Эскиз23"
  geometry: L1 (208, -200)-(-192, -200); L2 (-192, -200)-(-192, 0); L3 (-192, 0)-(208, 0); L4 (208, 0)-(208, -200); L5 (0, -200)-(16, -200) reference; 5 further points
  constraints: 8 end point, 4 midpoint, 2 coincident, 2 parallel, 1 collinear, 1 horizontal, 1 perpendicular
  dimensions: "d177" = 400 distance of L1.start L1.end; "d178" = 200 distance of L1.end L2.end
extrude "Выдавливание15" join sketch "Эскиз23" distance "d179" = 16; taper "d180" = 0 deg
revolve "Вращение1" stored, may be unused: angle "d200" = 90 deg
sketch "Эскиз24"
  geometry: L1 (-40, 4.848)-(-40, -11.152) reference; L2 (-42, 4.848)-(-42, -11.152) reference; L3 (-32, 2.848)-(-32, -9.152) reference; L4 (-40, 2.848)-(-40, -9.152) reference; L5 (-42, 251.848)-(-40, 251.848); L6 (-40, 251.848)-(-40, 249.848); L7 (-40, 249.848)-(-32, 249.848); L8 (-32, 249.848)-(-32, 251.848); L9 (-32, 251.848)-(-26, 251.848); L10 (-26, 251.848)-(-26, 246.848); L11 (-26, 246.848)-(-42, 246.848); L12 (-42, 246.848)-(-42, 251.848); L13 (-40, 4.848)-(-42, 4.848) reference; L14 (-32, 2.848)-(-40, 2.848) reference; L15 (-26, 4.848)-(-32, 4.848) reference; L16 (-52.753, 243.848)-(-14.167, 243.848); 2 further points
  constraints: 18 end point, 5 perpendicular, 3 parallel, 2 horizontal, 2 point on line, 1 collinear, 1 midpoint
  dimensions: "d202" = 16 diameter of L5 L16; "d203" = 2 distance between parallel lines of L5 L7; "d204" = 6 diameter of L11 L16; "d205" = 247 vertical distance of point (-42, -3.152) L16.start
revolve "Вращение2" sketch "Эскиз24" stored, may be unused: angle "d206" = 90 deg
node "РабПлоскость5"
sketch "Эскиз25"
  geometry: L1 (-15.55, -15.55)-(15.55, -15.55); L2 (15.55, -15.55)-(15.55, 15.55); L3 (15.55, 15.55)-(-15.55, 15.55); L4 (-15.55, 15.55)-(-15.55, -15.55); L5 (-17, -21.5)-(17, -21.5); L6 (21.5, -17)-(21.5, 17); L7 (17, 21.5)-(-17, 21.5); L8 (-21.5, 17)-(-21.5, -17); L9 (-17, -21.5)-(-21.5, -17); L10 (-21.5, 17)-(-17, 21.5); L11 (21.5, 17)-(17, 21.5); L12 (21.5, -17)-(17, -21.5); L13 (-17, -21.5)-(-15, -23.5); L14 (-15, -23.5)-(26, -23.5); L15 (-17, 21.5)-(-15, 23.5); L16 (-15, 23.5)-(26, 23.5); L17 (26, -15.291)-(26, 249.291) reference; L18 (26, 23.5)-(26, -23.5); C1 r 3 at (0, 0) reference; C2 r 8 at (0, 0) reference; C3 r 12 at (0, 0); C4 r 1.5 at (-15.55, -15.55); C5 r 1.5 at (-15.55, 15.55); C6 r 1.5 at (15.55, -15.55); C7 r 1.5 at (15.55, 15.55); A1 r 21.991 centre (0, 0) between (-15.55, -15.55) and (15.55, 15.55); 12 further points
  constraints: 34 end point, 10 point on line, 6 centre point, 6 coincident, 5 horizontal, 4 parallel, 3 equal length, 3 midpoint, 3 point on circle, 2 perpendicular, 2 vertical, 2 vertical alignment, 1 collinear, 1 horizontal alignment, 9 other
  dimensions: "d208" = 24 diameter of C3; "d209" = 3 diameter of C4; "d210" = 31.1 distance of L3.end L1.start; "d213" = 31.1 distance of L1.start point (-15.55, 15.55) (derived); "d216" = 31.1 distance of L1.start point (15.55, -15.55) (derived); "d219" = 43 distance of point (-21.5, 21.5) point (21.5, 21.5); "d220" = 43 distance of point (21.5, 21.5) point (21.5, -21.5); "d221" = 4.5 distance of L5.start point (-21.5, -21.5); "d222" = 4.5 distance of L8.end point (-21.5, -21.5) (derived); "d223" = 4.5 distance of L8.start point (-21.5, 21.5) (derived); "d224" = 4.5 distance of L7.end point (-21.5, 21.5) (derived); "d225" = 4.5 distance of L6.end point (21.5, 21.5) (derived); "d226" = 4.5 distance of L7.start point (21.5, 21.5) (derived); "d227" = 4.5 distance of L6.start point (21.5, -21.5) (derived); "d228" = 4.5 distance of L5.end point (21.5, -21.5) (derived); "d229" = 2 distance between parallel lines of L5 L14
extrude "Выдавливание16" new body sketch "Эскиз25" distance "d230" = 3; taper "d231" = 0 deg
sketch "Эскиз26"
  geometry: L1 (26, -23.5)-(26, 23.5) reference; L2 (-15, -23.5)-(26, -23.5) reference; L3 (-21.5, -17)-(-15, -23.5) reference; L4 (-21.5, 17)-(-21.5, -17) reference; L5 (-15, 23.5)-(-21.5, 17) reference; L6 (26, 23.5)-(-15, 23.5) reference; L7 (23, -23.5)-(23, 23.5); C1 r 1.5 at (15.55, 15.55) reference; C2 r 1.5 at (15.55, -15.55) reference; C3 r 1.5 at (-15.55, 15.55) reference; C4 r 1.5 at (-15.55, -15.55) reference; 1 further point
  constraints: 2 end point, 2 point on line, 1 perpendicular
  dimensions: "d232" = 3 distance between parallel lines of L1 L7
extrude "Выдавливание17" join sketch "Эскиз26" distance "d233" = 35; taper "d234" = 0 deg
sketch "Эскиз27"
  geometry: L1 (0, 0)-(0, 41) reference; L2 (0, 41)-(-38, 41) reference; L3 (-38, 38)-(-38, 41) reference; L4 (-3, 38)-(-38, 38) reference; L5 (-3, 0)-(-3, 38) reference; L6 (0, 0)-(-3, 0) reference; L7 (-3, 0)-(-38, 38); 1 further point
  constraints: 2 end point
extrude "Выдавливание18" join sketch "Эскиз27" distance "d235" = 2; taper "d236" = 0 deg
node "РабПлоскость6"
mirror "Зеркальное отражение4"
chamfer "Фаска9" distance "d237" = 1; stored, may be unused: second distance "d238" = 2, angle "d239" = 45 deg
chamfer "Фаска10" distance "d240" = 2; stored, may be unused: second distance "d241" = 2, angle "d242" = 45 deg
sketch "Эскиз29"
  geometry: L1 (-42.1, 280.288)-(-42.1, -3.288) reference; L2 (-35.692, -9.275)-(96.426, -0.265) reference; L3 (96.426, -0.265)-(102.9, 6.209) reference; L4 (102.9, 6.209)-(102.9, 270.791) reference; L5 (102.9, 270.791)-(96.426, 277.265) reference; L6 (96.426, 277.265)-(-35.692, 286.275) reference; L7 (75.05, 37.069)-(75.05, 38.5) reference; L8 (75.05, 38.5)-(82.75, 38.5) reference; L9 (82.75, 38.5)-(82.75, 37.069) reference; L10 (71.4, 42.576)-(71.4, 47.576) reference; L11 (71.4, 47.576)-(86.4, 47.576) reference; L12 (86.4, 47.576)-(86.4, 42.576) reference; L13 (86.4, 42.576)-(71.4, 42.576) reference; L14 (-24.95, 35.5)-(-24.95, 38.5) reference; L15 (-24.95, 38.5)-(-17.25, 38.5) reference; L16 (-17.25, 38.5)-(-17.25, 35.5) reference; L17 (-17.25, 35.5)-(-24.95, 35.5) reference; L18 (-28.6, 42.576)-(-28.6, 47.576) reference; L19 (-28.6, 47.576)-(-13.6, 47.576) reference; L20 (-13.6, 47.576)-(-13.6, 42.576) reference; L21 (-13.6, 42.576)-(-28.6, 42.576) reference; L22 (71.4, 229.424)-(71.4, 234.424) reference; L23 (71.4, 234.424)-(86.4, 234.424) reference; L24 (86.4, 234.424)-(86.4, 229.424) reference; L25 (86.4, 229.424)-(71.4, 229.424) reference; L26 (-28.6, 234.424)-(-13.6, 234.424) reference; L27 (-13.6, 234.424)-(-13.6, 229.424) reference; L28 (-13.6, 229.424)-(-28.6, 229.424) reference; L29 (-28.6, 229.424)-(-28.6, 234.424) reference; L30 (-17.25, 238.5)-(-24.95, 238.5) reference; L31 (-24.95, 238.5)-(-24.95, 241.5) reference; L32 (-24.95, 241.5)-(-17.25, 241.5) reference; L33 (-17.25, 241.5)-(-17.25, 238.5) reference; L34 (82.75, 239.931)-(82.75, 238.5) reference; L35 (82.75, 238.5)-(75.05, 238.5) reference; L36 (75.05, 238.5)-(75.05, 239.931) reference; L37 (-21.1, 24.652)-(-26.757, 30.309); C1 r 3 at (-21.1, 24.652) reference; C2 r 1.4 at (94.45, 267.898) reference; C3 r 1.4 at (63.35, 236.798) reference; C4 r 1.4 at (63.35, 9.102) reference; C5 r 1.4 at (63.35, 40.202) reference; C6 r 1.4 at (94.45, 40.202) reference; C7 r 1.4 at (94.45, 9.102) reference; C8 r 1.4 at (63.35, 267.898) reference; C9 r 1.4 at (94.45, 236.798) reference; C10 r 3 at (-21.1, 252.348) reference; C11 r 2 at (-26.757, 30.309); C12 r 1.5 at (-26.757, 30.309); C13 r 1.5 at (-21.1, 9.652); C14 r 1.5 at (-8.11, 32.152); A1 r 6 centre (-36.1, 280.288) between (-35.692, 286.275) and (-42.1, 280.288) reference; A2 r 6 centre (-36.1, -3.288) between (-42.1, -3.288) and (-35.692, -9.275) reference; A3 r 13 centre (78.9, 24.652) between (75.05, 37.069) and (82.75, 37.069) reference; A4 r 13 centre (78.9, 252.348) between (82.75, 239.931) and (75.05, 239.931) reference; A5 r 8 centre (-21.1, 24.652) between (-26.757, 30.309) and (-26.757, 30.309) reference; 1 further point
  constraints: 4 centre point, 2 end point, 2 equal radius, 1 coincident
  dimensions: "d243" = 4 diameter of C11; "d244" = 3 dimension on C11 C1; "d245" = 3 diameter of C12; "d246" = 45 deg angle of L14 L37
extrude "Выдавливание19" cut sketch "Эскиз29" distance "d247" = 13; taper "d248" = 0 deg
sketch "Эскиз30"
  geometry: C1 r 1.5 at (18.657, -21.343) reference; C2 r 2 at (18.657, -21.343); 1 further point
  constraints: 1 centre point, 1 coincident
  dimensions: "d249" = 4 diameter of C2
extrude "Выдавливание20" cut sketch "Эскиз30" distance "d250" = 4; taper "d251" = 0 deg
fillet "Сопряжение8" dims "d252" = 4
chamfer "Фаска11" distance "d253" = 2; stored, may be unused: second distance "d254" = 2, angle "d255" = 45 deg
fillet "Сопряжение9" dims "d256" = 1
chamfer "Фаска12" distance "d257" = 0.7; stored, may be unused: second distance "d258" = 2, angle "d259" = 45 deg
chamfer "Фаска13" distance "d260" = 0.75; stored, may be unused: second distance "d261" = 2, angle "d262" = 45 deg
sketch "Эскиз31"
  geometry: L1 (-0.106, 235.45)-(26, 235.212); L2 (26, 258.788)-(26, -24.788) reference; L3 (-0.106, 258.55)-(26, 258.788); L4 (26, -15.291)-(26, 249.291) reference; C1 r 8 at (0, 247) reference; C2 r 3 at (0, 247) reference; C3 r 6.55 at (0, 247); A1 r 11.55 centre (0, 247) between (-0.106, 258.55) and (-0.106, 235.45); 1 further point
  constraints: 4 end point, 2 centre point, 2 point on circle, 2 point on line, 2 tangent, 1 coincident, 1 equal length
  dimensions: "d263" = 13.1 diameter of C3; "d264" = 5 radial gap between concentric circles of C3 A1
extrude "Выдавливание21" new body sketch "Эскиз31" distance "d265" = 3; taper "d266" = 0 deg
sketch "Эскиз32"
  geometry: L1 (-0.106, -235.45)-(26, -235.212) reference; L2 (26, -235.212)-(26, -258.788) reference; L3 (26, -258.788)-(-0.106, -258.55) reference; L4 (23, -235.239)-(23, -258.761); C1 r 6.55 at (0, -247) reference; A1 r 11.55 centre (0, -247) between (-0.106, -235.45) and (-0.106, -258.55) reference; 1 further point
  constraints: 2 end point, 2 point on line, 1 vertical
  dimensions: "d267" = 3 distance between parallel lines of L2 L4
extrude "Выдавливание22" join sketch "Эскиз32" distance "d268" = 28; taper "d269" = 0 deg
sketch "Эскиз42"
  geometry: L1 (23, 235.239)-(23, 258.761) reference; L2 (23, 258.761)-(-0.106, 258.55) reference; L3 (-0.106, 235.45)-(23, 235.239) reference; L4 (23, 237.239)-(-6.583, 237.51); L5 (-0.106, 235.45)-(23, 235.239) reference; L6 (23, 258.761)-(23, 235.239) reference; C1 r 6.55 at (0, 247) reference; A1 r 11.55 centre (0, 247) between (-0.106, 258.55) and (-0.106, 235.45) reference; 1 further point
  constraints: 2 end point, 1 parallel, 1 point on circle, 1 point on line
  dimensions: "d339" = 2 distance between parallel lines of L3 L4
sketch "Эскиз43"
  geometry: L1 (23, 237.239)-(-6.583, 237.51) reference; L2 (23, 258.761)-(23, 235.239) reference; L3 (23, 237.239)-(23, 235.239); L4 (22, 237.248)-(22, 235.248); L5 (-0.106, 235.45)-(23, 235.239) reference; 1 further point
  constraints: 4 end point, 2 point on line, 2 vertical
  dimensions: "d340" = 1 distance between parallel lines of L2 L4
feature "Лофт2" sketch "Эскиз42", "Эскиз43" dims "d341" = 0, "d342" = 90 deg, "d343" = 0, "d344" = 90 deg
node "РабПлоскость8"
mirror "Зеркальное отражение6"
chamfer "Фаска19" distance "d345" = 5; stored, may be unused: second distance "d346" = 8, angle "d347" = 45 deg
sketch "Эскиз44"
  geometry: L1 (-32.1, 21.549)-(-32.1, -262.028) reference; L2 (-25.692, -268.014)-(106.426, -259.004) reference; L3 (106.426, -259.004)-(112.9, -252.53) reference; L4 (112.9, -252.53)-(112.9, 12.052) reference; L5 (112.9, 12.052)-(106.426, 18.525) reference; L6 (106.426, 18.525)-(-25.692, 27.535) reference; L7 (85.05, -221.67)-(85.05, -220.239) reference; L8 (85.05, -220.239)-(92.75, -220.239) reference; L9 (92.75, -220.239)-(92.75, -221.67) reference; L10 (81.4, -216.163)-(81.4, -211.163) reference; L11 (81.4, -211.163)-(96.4, -211.163) reference; L12 (96.4, -211.163)-(96.4, -216.163) reference; L13 (96.4, -216.163)-(81.4, -216.163) reference; L14 (-14.95, -223.239)-(-14.95, -220.239) reference; L15 (-14.95, -220.239)-(-7.25, -220.239) reference; L16 (-7.25, -220.239)-(-7.25, -223.239) reference; L17 (-7.25, -223.239)-(-14.95, -223.239) reference; L18 (-18.6, -216.163)-(-18.6, -211.163) reference; L19 (-18.6, -211.163)-(-3.6, -211.163) reference; L20 (-3.6, -211.163)-(-3.6, -216.163) reference; L21 (-3.6, -216.163)-(-18.6, -216.163) reference; L22 (81.4, -29.315)-(81.4, -24.315) reference; L23 (81.4, -24.315)-(96.4, -24.315) reference; L24 (96.4, -24.315)-(96.4, -29.315) reference; L25 (96.4, -29.315)-(81.4, -29.315) reference; L26 (-18.6, -24.315)-(-3.6, -24.315) reference; L27 (-3.6, -24.315)-(-3.6, -29.315) reference; L28 (-3.6, -29.315)-(-18.6, -29.315) reference; L29 (-18.6, -29.315)-(-18.6, -24.315) reference; L30 (-7.25, -20.239)-(-14.95, -20.239) reference; L31 (-14.95, -20.239)-(-14.95, -17.239) reference; L32 (-14.95, -17.239)-(-7.25, -17.239) reference; L33 (-7.25, -17.239)-(-7.25, -20.239) reference; L34 (92.75, -18.808)-(92.75, -20.239) reference; L35 (92.75, -20.239)-(85.05, -20.239) reference; L36 (85.05, -20.239)-(85.05, -18.808) reference; L37 (0, 19.522)-(0, 0) reference; L38 (-25, 19.251)-(0, 19.513) reference; C1 r 1.5 at (-16.757, -228.43) reference; C2 r 3 at (-11.1, -234.087) reference; C3 r 1.4 at (104.45, 9.159) reference; C4 r 1.4 at (73.35, -21.941) reference; C5 r 1.4 at (73.35, -249.637) reference; C6 r 1.4 at (73.35, -218.537) reference; C7 r 1.4 at (104.45, -218.537) reference; C8 r 1.4 at (104.45, -249.637) reference; C9 r 1.4 at (73.35, 9.159) reference; C10 r 1.4 at (104.45, -21.941) reference; C11 r 3 at (-11.1, -6.391) reference; C12 r 1.5 at (-11.1, 8.609); C13 r 2 at (-4, 17.471); C14 r 4 at (-4, 17.471); A1 r 6 centre (-26.1, 21.549) between (-25.692, 27.535) and (-32.1, 21.549) reference; A2 r 6 centre (-26.1, -262.028) between (-32.1, -262.028) and (-25.692, -268.014) reference; A3 r 13 centre (88.9, -234.087) between (85.05, -221.67) and (92.75, -221.67) reference; A4 r 13 centre (88.9, -6.391) between (92.75, -18.808) and (85.05, -18.808) reference; 1 further point
  constraints: 3 centre point, 2 tangent
  dimensions: "d348" = 3 diameter of C12; "d349" = 4 diameter of C13; "d350" = 2 radial gap between concentric circles of C13 C14
extrude "Выдавливание29" join sketch "Эскиз44" distance "d351" = 2; taper "d352" = 0 deg
fillet "Сопряжение18" dims "d353" = 1
sketch "Эскиз45"
  geometry: C1 r 2 at (16, 17.471) reference; C2 r 2.7 at (8.9, 8.609) reference; C3 r 1.5 at (8.9, 8.609); 1 further point
  constraints: 1 centre point, 1 coincident
  dimensions: "d354" = 3 diameter of C3
extrude "Выдавливание30" cut sketch "Эскиз45" distance "d355" = 5; taper "d356" = 0 deg
chamfer "Фаска21" distance "d363" = 2; stored, may be unused: second distance "d364" = 8, angle "d365" = 45 deg
fillet "Сопряжение20" dims "d367" = 5
sketch "Эскиз47"
  geometry: C1 r 6.55 at (0, 247) reference; C2 r 8.55 at (0, 247); 1 further point
  constraints: 1 centre point
  dimensions: "d368" = 2 radial gap between concentric circles of C1 C2
extrude "Выдавливание32" join sketch "Эскиз47" distance "d369" = 1.3; taper "d370" = 0 deg
sketch "Эскиз48"
  geometry: C1 r 8.55 at (0, 0) reference; C2 r 6.55 at (0, 0) reference; C3 r 4 at (0, 0); 1 further point
  constraints: 1 centre point, 1 coincident
  dimensions: "d371" = 8 diameter of C3
extrude "Выдавливание33" join sketch "Эскиз48" distance "d372" = 2; taper "d373" = 0 deg
fillet "Сопряжение21" dims "d374" = 2
chamfer "Фаска22" distance "d375" = 0.8; stored, may be unused: second distance "d376" = 8, angle "d377" = 45 deg
chamfer "Фаска23" distance "d379" = 0.5; stored, may be unused: second distance "d380" = 8, angle "d381" = 45 deg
